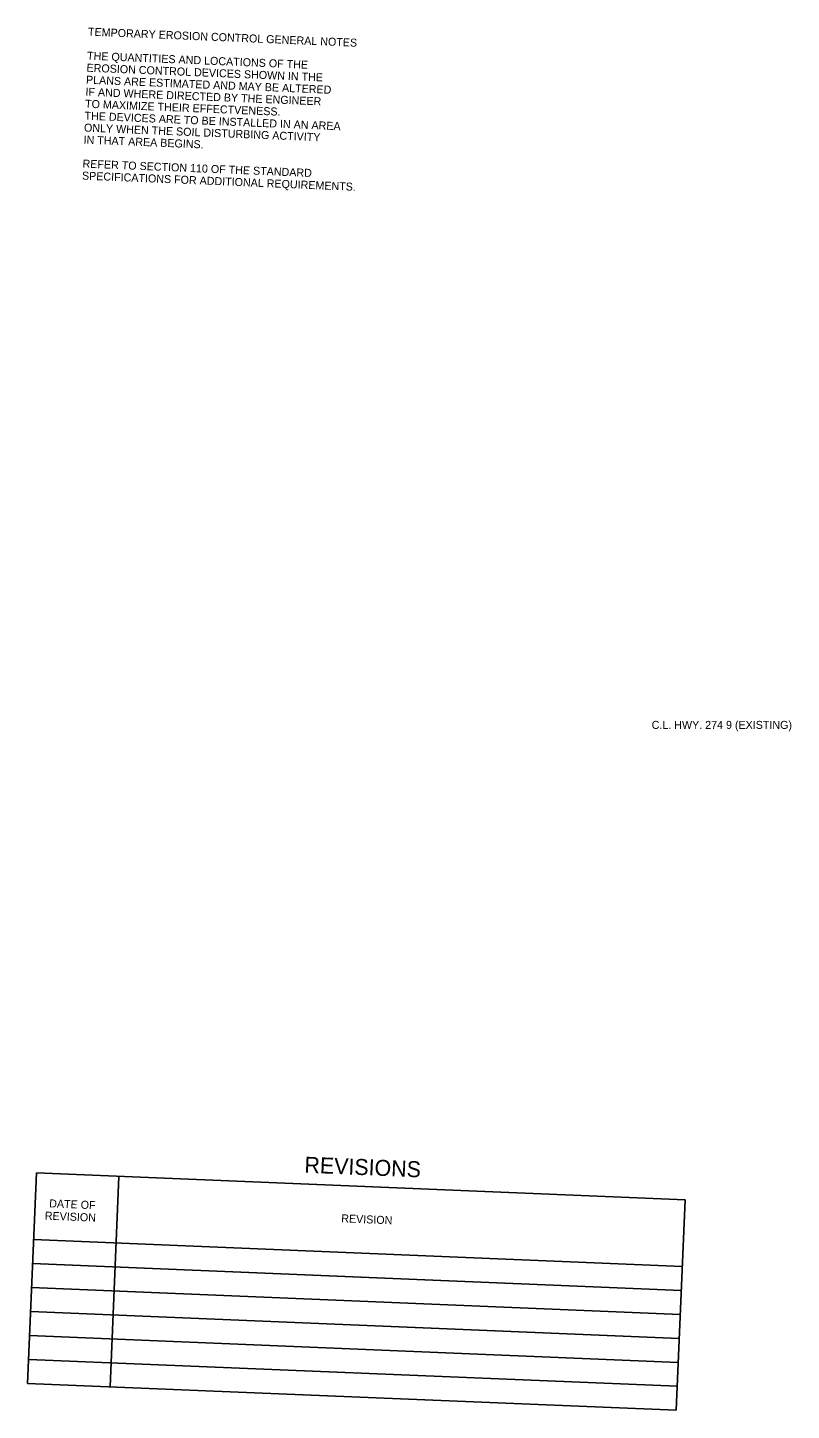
# Model space of a CAD drawing. Extents: x 1141845 to 1143440, y 1657054 to 1658137.
# Drawn here: x 1141845 to 1142418, y 1657100 to 1658137 of the extents above; entities that cross this region are included whole.
import ezdxf

# ---------------------------------------------------------------- set-up
doc = ezdxf.new("R2010")
doc.units = 0
doc.layers.add('S_PRIMARY_CTL', color=7, linetype='Continuous')
doc.layers.add('S_SECONDARY_CTL', color=7, linetype='Continuous')

msp = doc.modelspace()

# ---------------------------------------------------------------- linework, layer by layer
at = {"layer": 'S_SECONDARY_CTL'}
for p, q in [((1141851.9, 1657278.2), (1141845.3, 1657120.3)), ((1141851.9, 1657278.2), (1142338.3, 1657258)), ((1141913.6, 1657275.6), (1141907.1, 1657117.7)), ((1142338.3, 1657258), (1142331.7, 1657100.2)), ((1141849.8, 1657228.2), (1142336.2, 1657208.1)), ((1141849, 1657210.2), (1142335.4, 1657190.1)), ((1141848.3, 1657192.2), (1142334.7, 1657172.1)), ((1141847.6, 1657174.2), (1142334, 1657154.1)), ((1141846.8, 1657156.3), (1142333.2, 1657136.1)), ((1141846.1, 1657138.3), (1142332.5, 1657118.2)), ((1141845.3, 1657120.3), (1142331.7, 1657100.2))]:
    msp.add_line(p, q, dxfattribs=at)

# ---------------------------------------------------------------- texts
at = {"layer": 'S_PRIMARY_CTL'}
for s, p in [('TEMPORARY EROSION CONTROL GENERAL NOTES', (1141890.5, 1658130.9)), ('THE QUANTITIES AND LOCATIONS OF THE', (1141889.8, 1658112.9)), ('PLANS ARE ESTIMATED AND MAY BE ALTERED ', (1141889, 1658094.9)), ('EROSION CONTROL DEVICES SHOWN IN THE ', (1141889.4, 1658103.9)), ('IF AND WHERE DIRECTED BY THE ENGINEER ', (1141888.6, 1658085.9)), ('TO MAXIMIZE THEIR EFFECTVENESS. ', (1141888.3, 1658076.9)), ('THE DEVICES ARE TO BE INSTALLED IN AN AREA ', (1141887.9, 1658067.9)), ('ONLY WHEN THE SOIL DISTURBING ACTIVITY', (1141887.5, 1658059)), ('IN THAT AREA BEGINS.', (1141887.2, 1658050)), ('SPECIFICATIONS FOR ADDITIONAL REQUIREMENTS.', (1141886, 1658023)), ('REFER TO SECTION 110 OF THE STANDARD ', (1141886.4, 1658032))]:
    msp.add_text(s, height=6, rotation=357.6311, dxfattribs=at).set_placement(p)
msp.add_text('C.L. HWY. 274 9 (EXISTING)', height=6, dxfattribs=at).set_placement((1142313.3, 1657611.1))
at = {"layer": 'S_SECONDARY_CTL'}
for s, height, p in [('REVISIONS', 12, (1142052.7, 1657278.4)), ('DATE OF', 6, (1141861.4, 1657252.4)), ('REVISION', 6, (1141858.1, 1657243.2)), ('REVISION', 6, (1142080.4, 1657241.2))]:
    msp.add_text(s, height=height, rotation=357.6311, dxfattribs=at).set_placement(p)

doc.saveas('drawing.dxf')
